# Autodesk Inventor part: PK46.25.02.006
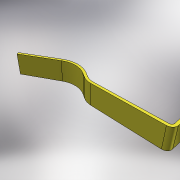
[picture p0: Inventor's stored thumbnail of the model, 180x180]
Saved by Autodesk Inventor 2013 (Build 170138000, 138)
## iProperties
Created: 2005-04
Part Number: PK46.25.02.006
Material: Steel, Mild
Document SubType Name: Sheet Metal
Designer: salex
Manufacturer: Standard
Standards Organization: Custom
Density: 7.86 g/cm^3
Sheet Metal Rule: Default
Mass: 33608.8 g
Surface Area: 4874.42 cm^2
Volume: 4275.93 cm^3
Author: salex
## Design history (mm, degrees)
node "ФлнОтгиб1"
body "Solid1"
sketch "Эскиз1"
  geometry: L1 (0, 0)-(281.548, 151.603); L2 (493.9, 143.842)-(527.12, 122.69); L3 (605, 100)-(1145, 100); L4 (1145, 100)-(1145, 260); L5 (281.548, 151.603)-(390, 210); L6 (510.51, 133.266)-(390, 210); A1 r 210 centre (381.109, -33.296) between (493.9, 143.842) and (281.548, 151.603); A2 r 145 centre (605, 245) between (527.12, 122.69) and (605, 100)
  constraints: 12 end point, 5 tangent, 4 point on circle, 2 centre point, 2 collinear, 1 horizontal, 1 midpoint, 1 perpendicular, 1 other
  dimensions: "d0" = 160 distance of L3.end L4.end; "d1" = 145 radius of A2; "d2" = 215 horizontal distance of L5.end A2.centre; "d3" = 35 vertical distance of L5.end A2.centre; "d4" = 540 distance from line of A2.centre L4; "d5" = 605 horizontal distance of A2.centre L1.start; "d6" = 210 radius of A1; "d15" = 245 vertical distance of A2.centre L1.start
feature "Плакирование1" dims "d8" = 160, "d9" = 20 (= BendReliefWidth), "d11" = 40 (= MinimumRemnant), "d13" = 20 (= BendRadius), "d14" = 20, "Thickness" = 20
feature "Изгиб1" dims "d9" = 20 (= BendReliefWidth), "d10" = 10 (= BendReliefDepth), "d11" = 40 (= MinimumRemnant), "d12" = 20 (= BendRadius), "d13" = 20 (= BendRadius), "d14" = 20, "SeamGap" = 0.01, "Thickness" = 20
other parameters: "BendRadius" = 20 (= Thickness)
